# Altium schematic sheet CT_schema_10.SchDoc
size 308 x 210 mm
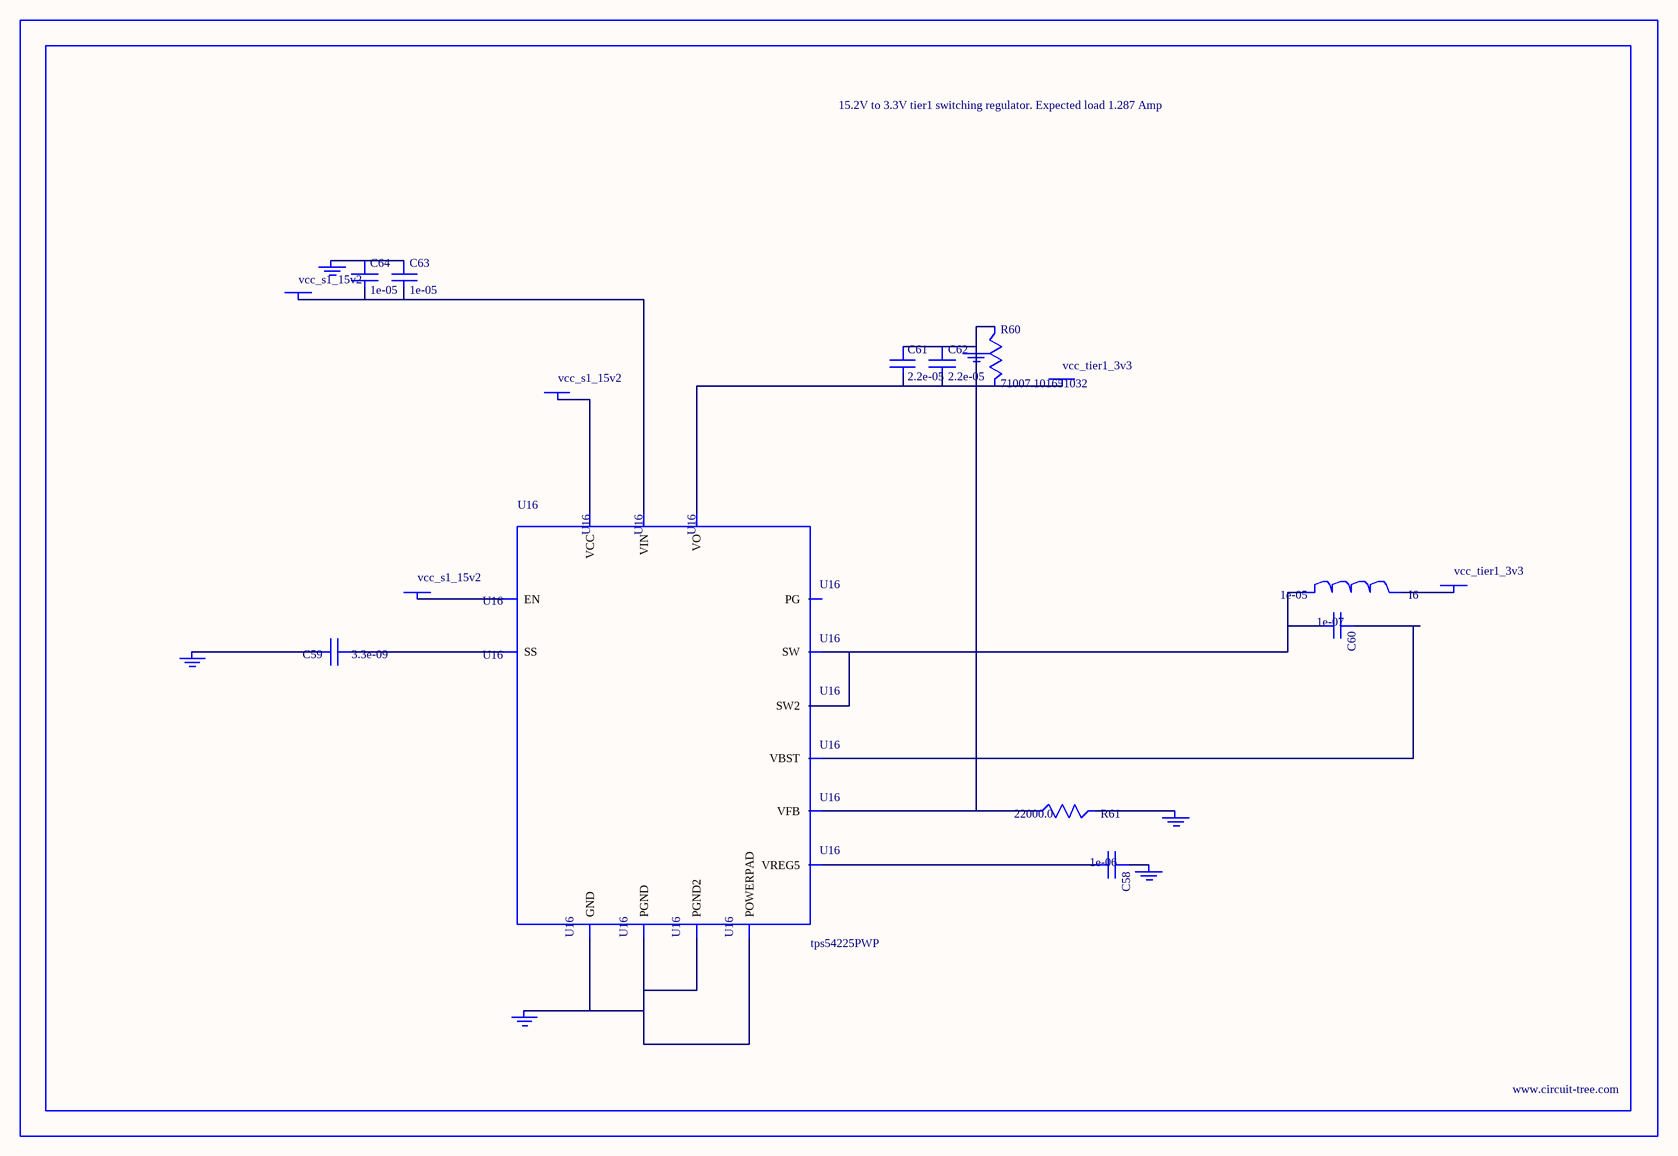
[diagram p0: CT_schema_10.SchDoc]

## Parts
BORDER9  (no value)
C58  1e-06  [C0603]
C59  3.3e-09  [C0402]
C60  1e-07  [C0402]
C61  2.2e-05  [C1210]
C62  2.2e-05  [C1210]
C63  1e-05  [C1206]
C64  1e-05  [C1206]
GND_INSTANCE_9_0  (no value)
GND_INSTANCE_9_1  (no value)
GND_INSTANCE_9_2  (no value)
GND_INSTANCE_9_3  (no value)
GND_INSTANCE_9_4  (no value)
GND_INSTANCE_9_5  (no value)
I6  1e-05  [IND_PM3316]
POWER_INSTANCE_9_0  vcc_tier1_3v3
POWER_INSTANCE_9_1  vcc_s1_15v2
POWER_INSTANCE_9_2  vcc_tier1_3v3
POWER_INSTANCE_9_3  vcc_s1_15v2
POWER_INSTANCE_9_4  vcc_s1_15v2
R60  71007.101651032  [R0603]
R61  22000.0  [R0603]
U16  tps54225PWP  [HTSSOP14]

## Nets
NetC58_1: C58.1 GND_INSTANCE_9_2.0(GND)
NetC58_2: C58.2 U16.3(VREG5)
NetC59_1: C59.1 U16.4(SS)
NetC59_2: C59.2 GND_INSTANCE_9_3.0(GND)
NetC60_1: C60.1 U16.12(VBST)
NetC60_2: C60.2 I6.1 U16.10(SW) U16.11(SW2)
NetC61_1: C61.1 C62.1 GND_INSTANCE_9_0.0(GND) R60.1 R61.1 U16.2(VFB)
NetC61_2: C61.2 C62.2 POWER_INSTANCE_9_0.0(PWR) R60.2 U16.1(VO)
NetC63_1: C63.1 C64.1 GND_INSTANCE_9_5.0(GND)
NetC63_2: C63.2 C64.2 POWER_INSTANCE_9_3.0(PWR) U16.13(VIN)
NetGND_INSTANCE_9_1_0: GND_INSTANCE_9_1.0(GND) R61.2
NetGND_INSTANCE_9_4_0: GND_INSTANCE_9_4.0(GND) U16.5(GND) U16.8(PGND) U16.9(PGND2) U16.15(POWERPAD)
NetI6_2: I6.2 POWER_INSTANCE_9_2.0(PWR)
NetPOWER_INSTANCE_9_1_0: POWER_INSTANCE_9_1.0(PWR) U16.7(EN)
NetPOWER_INSTANCE_9_4_0: POWER_INSTANCE_9_4.0(PWR) U16.14(VCC)

Not connected (* = marked no-connect by the designer): U16 6(PG)

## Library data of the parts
BORDER9 = BORDER_PAGE9
C58 = C0603C105K3RACTU
C59 = C0402C332K3RAC
C60 = C0402C104K3RACTU
C61 C62 = GRM32ER61E226ME15L
C63 C64 = C1206C106K3RACTU
GND_INSTANCE_9_0-GND_INSTANCE_9_5 = GND
I6 = PM3316-100M-RC
POWER_INSTANCE_9_0-POWER_INSTANCE_9_4 = PWR
R60 = R60
R61 = RC0603JR-0722KL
